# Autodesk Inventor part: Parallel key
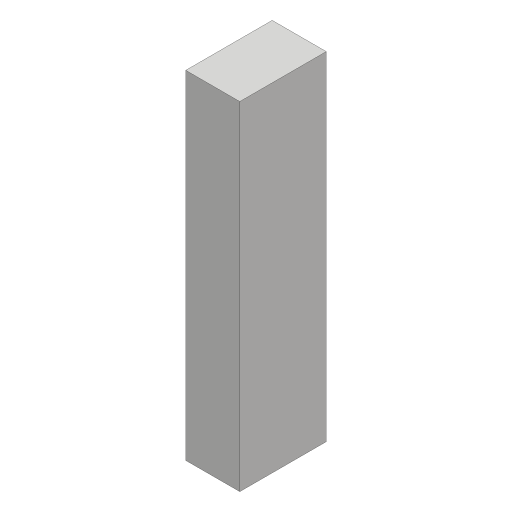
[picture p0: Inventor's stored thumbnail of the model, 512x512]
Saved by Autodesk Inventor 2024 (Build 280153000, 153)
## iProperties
Created: 2016-05
Part Number: Parallel key
Material: Generic
Document SubType Name: Modeling
Designer: CADCIM
Density: 1 g/cm^3
Appearance: Default
Author: CADCIM
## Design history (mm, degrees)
sketch "Sketch1"
  geometry: L1 (0, 0)-(16, 0); L2 (16, 0)-(16, -62.5); L3 (16, -62.5)-(0, -62.5); L4 (0, -62.5)-(0, 0)
  constraints: 8 end point, 2 parallel, 1 horizontal, 1 perpendicular
  dimensions: "d0" = 62.5 distance of L3.end L1.start; "d1" = 16 distance of L2.end L3.end
extrude "Extrusion1" new body sketch "Sketch1" distance "d2" = 10; taper "d3" = 0 deg
body "Solid1"
